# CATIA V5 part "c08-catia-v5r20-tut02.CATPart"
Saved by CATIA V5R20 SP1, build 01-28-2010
Part number: Part1
Bounding box of the stored display mesh (mm): x -50.5 to 35, y -44.738 to 44.738, z 0 to 30.5
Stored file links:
  D:\v5_r20\psrt_files_downloaded\c08-catia-v5r20-prt\c08-catia-v5r20-tut02.CATPart
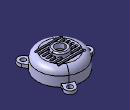
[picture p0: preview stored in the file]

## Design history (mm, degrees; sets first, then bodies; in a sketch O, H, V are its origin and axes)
Body1 (main body)
  Sketch1 on yz-plane, origin (0, 0, 0), H (0, 1, 0), V (0, 0, 1)
    line L1 (0, 0) -> (35, 0)
    line L2 (35, 0) -> (35, 15)
    arc A1 centre (25, 15) radius 10 from (35, 15) to (25, 25) ccw
    line L3 (25, 25) -> (0, 25)
    point P5 (0, 25)
    line L4 (0, 25) -> (0, 0)
    axis line L5 (0, 70.1891) -> (0, -36.6898)
    point P6 (0, 70.1891)
    "Radius" L2 L5 = 35
    distance L1 L3 = 25
    radius A1 = 10
    horizontal: L1 H
    vertical: L2 V, L4 V, L5 V
    tangency: A1 L2, L3 A1
    coincidence: P5 V, P6 V
  Shaft1: profile Sketch1, axis Sketch1.L5, angle 360
  Shell1: IntOffset 2.5, Face face of Shaft1, ExtOffset 0
  Sketch2 on face of Shaft1, origin (0, 0, 0), H (1, 0, 0), V (0, -1, 0)
    projected circle E1 centre (0, 0) radius 35 from edge [face of Shaft1 | face of Shaft1]
    projected arc E2 centre (0, 0) radius 35 from (-34.0735, 8) to (-34.0735, -8) ccw from edge [face of Shaft1 | face of Shaft1]
    point P1 (-34.0735, 8)
    line L1 (-34.0735, 8) -> (-42.5, 8)
    arc A1 centre (-42.5, 0) radius 8 from (-42.5, 8) to (-42.5, -8) ccw
    point P3 (-42.5, 0)
    line L2 (-42.5, -8) -> (-34.0735, -8)
    point P5 (-34.0735, -8)
    circle A2 centre (-42.5, 0) radius 4
    distance P3 V = 42.5
    radius A1 = 8
    radius A2 = 4
    coincidence: P1 E1, P5 E1, P3 H
    horizontal: L1 H, L2 H
    tangency: A1 L1, L2 A1
  Pad1: profile Sketch2, direction (0, 0, 1), length 5
  CircPattern1: of Pad1, instances 3, angular step 120 {= 360.0*1 deg/CircPattern1.AngularNumber}, axis from face of Shaft1
  Sketch3 on face of Shaft1, origin (0, 0, 25), H (1, 0, 0), V (0, 1, 0)
    construction line L1 (-20, -18) -> (20, -18)
    point P2 (20, -18)
    line L2 (-20, -16.25) -> (20, -16.25)
    line L3 (20, -19.75) -> (-20, -19.75)
    arc A1 centre (20, -18) radius 1.75 from (20, -16.25) to (20, -19.75) cw
    arc A2 centre (-20, -18) radius 1.75 from (-20, -19.75) to (-20, -16.25) cw
    length L1 = 40
    distance H L1 = 18
    distance P2 V = 20
    distance L3 L2 = 3.5
    horizontal: L1 H
    tangency: A1 L2, A2 L2, A1 L3, A2 L3
    parallelism: L1 L2
  Pocket1: profile Sketch3, direction (0, 0, -1), length 5
  RectPattern1: of Pocket1, direction 1 instances 7, spacing 6, along yz-plane
  Sketch4 on face of Shell1, origin (0, 0, 22.5), H (1, 0, 0), V (0, -1, 0)
    circle A1 centre (0, 0) radius 12.5
    radius A1 = 12.5
  Pad2: profile Sketch4, direction (0, 0, 1), length 8
  Fillet1: radius 2, on edge [end face of Pad2 | face of Pad2 from Sketch4.A1]
  Sketch5 on face of Pad2, origin (0, 0, 22.5), H (1, 0, 0), V (0, -1, 0)
    circle A1 centre (0, 0) radius 7.5
    radius A1 = 7.5
  Pocket2: profile Sketch5, direction (0, 0, 1), through (limit type 3)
